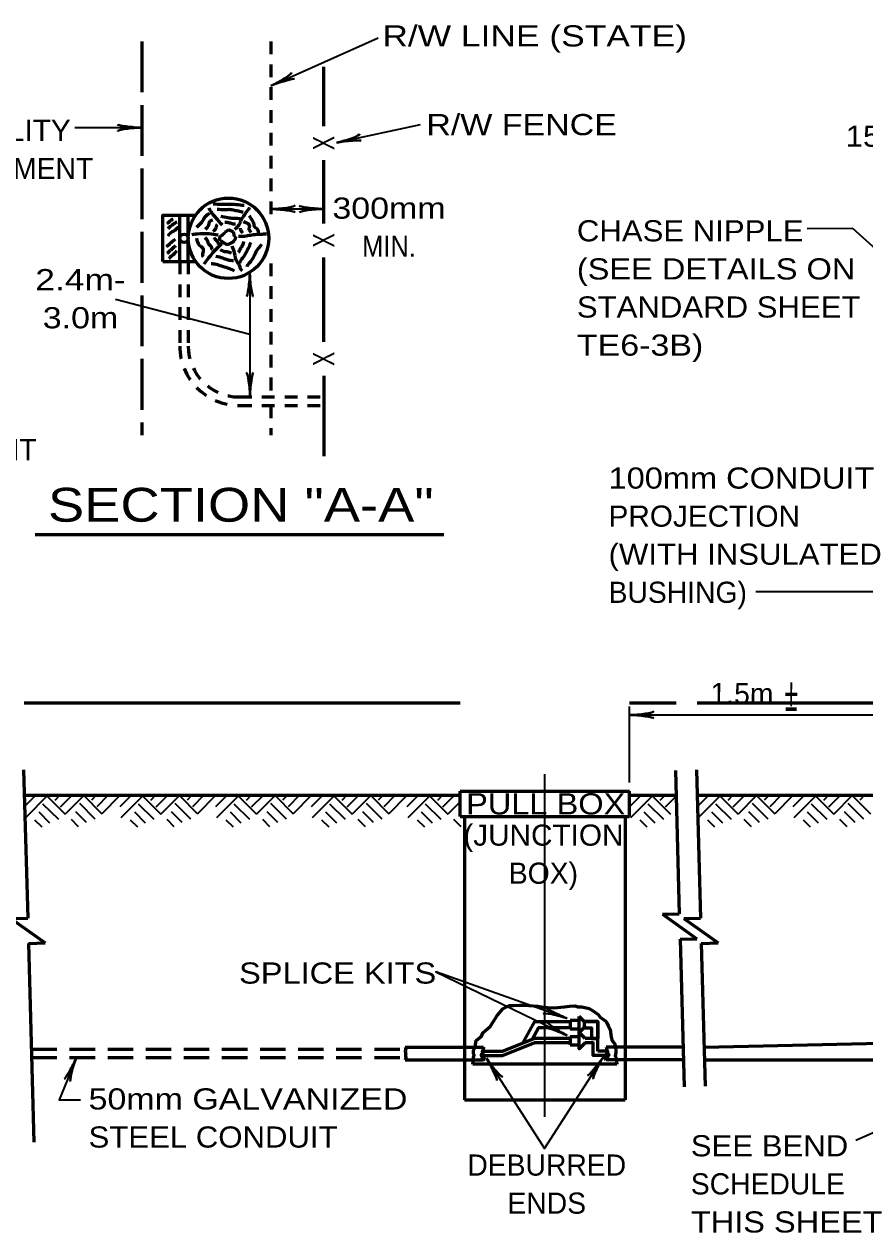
# Model space of a CAD drawing. Extents: x -111 to 744, y -77 to 467.
# Drawn here: x 90.6 to 209.8, y 149.5 to 320.9 of the extents above; entities that cross this region are included whole.
import ezdxf
from ezdxf.enums import TextEntityAlignment as Align

# ---------------------------------------------------------------- set-up
doc = ezdxf.new("R2010")
doc.units = 0
doc.header["$LTSCALE"] = 1.2
for name, pattern in [('LONG_DASHED', [7.5, 6, -1.5]), ('MEDIUM_DASHED', [4.5, 3, -1.5]), ('SHORT_DASHED', [2.7, 1.5, -1.2])]:
    doc.linetypes.add(name, pattern=pattern)
doc.layers.add('1', color=7, linetype='Continuous', lineweight=53)

msp = doc.modelspace()

# ---------------------------------------------------------------- linework, layer by layer
at = {"layer": '1', "lineweight": 35}
for p, q in [((125.55, 312.119), (140.793, 318.948)), ((107.25, 306.191), (97.784, 306.191)), ((134.901, 304.08), (146.774, 306.631)), ((125.55, 294.666), (133.05, 294.666)), ((208.049, 291.917), (201.596, 291.865)), ((232.956, 269.288), (208.049, 291.917)), ((122.588, 285.687), (122.588, 268.01)), ((122.588, 276.849), (103.55, 281.816)), ((218.647, 240.391), (194.294, 240.391)), ((176.408, 213.331), (176.408, 224.131)), ((176.408, 222.931), (214.639, 222.931)), ((164.408, 165.93), (164.408, 214.531)), ((92.192, 211.483), (90.608, 209.899)), ((93.896, 211.483), (90.752, 208.339)), ((93.776, 211.483), (96.416, 208.843)), ((95.6, 211.483), (94.928, 210.787)), ((97.328, 211.483), (95.672, 209.827)), ((99.032, 211.483), (96.416, 208.843)), ((99.032, 211.483), (101.6, 208.915)), ((100.736, 211.483), (100.112, 210.859)), ((102.464, 211.483), (100.88, 209.899)), ((104.168, 211.483), (101.6, 208.915)), ((105.752, 211.483), (104.168, 209.899)), ((107.456, 211.483), (104.312, 208.339)), ((107.336, 211.483), (109.976, 208.843)), ((109.16, 211.483), (108.488, 210.787)), ((110.888, 211.483), (109.232, 209.827)), ((112.592, 211.483), (109.976, 208.843)), ((112.592, 211.483), (115.16, 208.915)), ((114.296, 211.483), (113.672, 210.859)), ((116.024, 211.483), (114.44, 209.899)), ((117.728, 211.483), (115.16, 208.915)), ((119.312, 211.483), (117.728, 209.899)), ((121.016, 211.483), (117.872, 208.339)), ((120.896, 211.483), (123.536, 208.843)), ((122.72, 211.483), (122.048, 210.787)), ((124.448, 211.483), (122.792, 209.827)), ((126.152, 211.483), (123.536, 208.843)), ((126.152, 211.483), (128.72, 208.915)), ((127.856, 211.483), (127.232, 210.859)), ((129.584, 211.483), (128, 209.899)), ((131.288, 211.483), (128.72, 208.915)), ((132.872, 211.483), (131.288, 209.899)), ((134.576, 211.483), (131.432, 208.339)), ((134.456, 211.483), (137.096, 208.843)), ((136.28, 211.483), (135.608, 210.787)), ((138.008, 211.483), (136.352, 209.827)), ((139.712, 211.483), (137.096, 208.843)), ((139.712, 211.483), (142.28, 208.915)), ((141.416, 211.483), (140.792, 210.859)), ((143.144, 211.483), (141.56, 209.899)), ((144.848, 211.483), (142.28, 208.915)), ((146.432, 211.483), (144.848, 209.899)), ((148.136, 211.483), (144.992, 208.339)), ((148.016, 211.483), (150.656, 208.843)), ((149.84, 211.483), (149.168, 210.787)), ((151.568, 211.483), (149.912, 209.827)), ((177.992, 211.483), (176.408, 209.899)), ((179.696, 211.483), (176.552, 208.339)), ((179.576, 211.483), (182.216, 208.843)), ((181.4, 211.483), (180.728, 210.787)), ((183.128, 211.483), (181.472, 209.827)), ((187.592, 211.483), (186.008, 209.899)), ((189.296, 211.483), (186.152, 208.339)), ((189.176, 211.483), (191.816, 208.843)), ((191, 211.483), (190.328, 210.787)), ((192.728, 211.483), (191.072, 209.827)), ((194.432, 211.483), (191.816, 208.843)), ((194.432, 211.483), (197, 208.915)), ((196.136, 211.483), (195.512, 210.859)), ((197.864, 211.483), (196.28, 209.899)), ((199.568, 211.483), (197, 208.915)), ((201.152, 211.483), (199.568, 209.899)), ((202.856, 211.483), (199.712, 208.339)), ((202.736, 211.483), (205.376, 208.843)), ((204.56, 211.483), (203.888, 210.787)), ((206.288, 211.483), (204.632, 209.827)), ((207.992, 211.483), (205.376, 208.843)), ((207.992, 211.483), (210.56, 208.915)), ((209.696, 211.483), (209.072, 210.859)), ((92.648, 209.179), (94.184, 207.643)), ((93.2, 210.331), (95.432, 208.123)), ((97.856, 209.251), (99.392, 207.715)), ((98.408, 210.403), (100.616, 208.195)), ((106.208, 209.179), (107.744, 207.643)), ((106.76, 210.331), (108.992, 208.123)), ((111.416, 209.251), (112.952, 207.715)), ((111.968, 210.403), (114.176, 208.195)), ((119.768, 209.179), (121.304, 207.643)), ((120.32, 210.331), (122.552, 208.123)), ((124.976, 209.251), (126.512, 207.715)), ((125.528, 210.403), (127.736, 208.195)), ((133.328, 209.179), (134.864, 207.643)), ((133.88, 210.331), (136.112, 208.123)), ((138.536, 209.251), (140.072, 207.715)), ((139.088, 210.403), (141.296, 208.195)), ((146.888, 209.179), (148.424, 207.643)), ((147.44, 210.331), (149.672, 208.123)), ((152.408, 210.611), (150.656, 208.843)), ((178.448, 209.179), (179.984, 207.643)), ((179, 210.331), (181.232, 208.123)), ((188.048, 209.179), (189.584, 207.643)), ((188.6, 210.331), (190.832, 208.123)), ((193.256, 209.251), (194.792, 207.715)), ((193.808, 210.403), (196.016, 208.195)), ((201.608, 209.179), (203.144, 207.643)), ((202.16, 210.331), (204.392, 208.123)), ((206.816, 209.251), (208.352, 207.715)), ((207.368, 210.403), (209.576, 208.195)), ((92.048, 208.075), (93.08, 207.067)), ((97.232, 208.147), (98.264, 207.115)), ((105.608, 208.075), (106.64, 207.067)), ((110.792, 208.147), (111.824, 207.115)), ((119.168, 208.075), (120.2, 207.067)), ((124.352, 208.147), (125.384, 207.115)), ((132.728, 208.075), (133.76, 207.067)), ((137.912, 208.147), (138.944, 207.115)), ((146.288, 208.075), (147.32, 207.067)), ((151.472, 208.147), (152.504, 207.115)), ((177.848, 208.075), (178.88, 207.067)), ((187.448, 208.075), (188.48, 207.067)), ((192.632, 208.147), (193.664, 207.115)), ((201.008, 208.075), (202.04, 207.067)), ((206.192, 208.147), (207.224, 207.115))]:
    msp.add_line(p, q, dxfattribs=at)
at = {"layer": '1', "linetype": 'LONG_DASHED'}
msp.add_line((107.25, 318.41), (107.25, 262.61), dxfattribs=at)
at = {"layer": '1', "linetype": 'SHORT_DASHED'}
for p, q in [((125.55, 318.41), (125.55, 292.897)), ((112.65, 287.21), (112.65, 275.21)), ((113.85, 287.21), (113.85, 275.21)), ((125.55, 286.952), (125.55, 268.01)), ((121.05, 268.01), (133.05, 268.01)), ((121.05, 266.81), (133.05, 266.81)), ((125.55, 266.81), (125.55, 262.61))]:
    msp.add_line(p, q, dxfattribs=at)
at = {"layer": '1'}
for p, q in [((133.05, 306.41), (133.05, 314.81)), ((133.05, 292.61), (133.05, 301.61)), ((112.65, 287.21), (112.65, 293.81)), ((113.85, 287.21), (113.85, 293.81)), ((110.25, 287.21), (114.902, 287.21)), ((133.05, 275.81), (133.05, 287.81)), ((133.05, 271.01), (133.05, 259.61)), ((92.14, 248.5), (150.088, 248.5)), ((90.608, 224.648), (152.408, 224.648)), ((176.408, 224.648), (183.008, 224.648)), ((186.008, 224.648), (214.639, 224.648)), ((90.509, 215.129), (91.087, 194.13)), ((182.912, 215.047), (183.47, 194.73)), ((185.91, 215.129), (186.487, 194.13)), ((90.608, 211.531), (152.408, 211.531)), ((152.408, 208.531), (152.408, 212.131)), ((152.408, 212.131), (176.408, 212.131)), ((176.408, 208.531), (176.408, 212.131)), ((176.408, 211.531), (183.008, 211.531)), ((186.008, 211.531), (214.639, 211.531)), ((152.408, 208.531), (176.408, 208.531)), ((153.008, 208.531), (153.008, 168.331)), ((175.808, 208.531), (175.808, 168.331)), ((88.688, 194.064), (91.087, 194.13)), ((88.688, 194.064), (93.585, 190.597)), ((181.071, 194.664), (183.47, 194.73)), ((181.071, 194.664), (185.968, 191.197)), ((184.088, 194.064), (186.487, 194.13)), ((184.088, 194.064), (188.985, 190.597)), ((91.186, 190.531), (93.585, 190.597)), ((91.186, 190.531), (91.961, 162.335)), ((183.569, 191.131), (185.968, 191.197)), ((183.569, 191.131), (184.145, 170.207)), ((186.586, 190.531), (188.985, 190.597)), ((186.586, 190.531), (187.142, 170.29)), ((170.115, 179.321), (169.26, 180.176)), ((169.26, 177.879), (169.26, 180.176)), ((168.007, 179.627), (169.26, 179.627)), ((168.007, 178.428), (169.26, 178.428)), ((170.212, 178.831), (169.26, 177.879)), ((158.408, 175.231), (162.908, 177.031)), ((168.007, 177.031), (162.908, 177.031)), ((168.007, 177.331), (168.007, 176.131)), ((168.007, 177.331), (169.26, 177.331)), ((170.108, 177.031), (169.26, 177.879)), ((171.908, 177.031), (170.108, 177.031)), ((171.908, 175.231), (171.908, 177.031)), ((144.608, 175.831), (155.708, 175.831)), ((155.503, 175.231), (158.408, 175.231)), ((158.408, 174.631), (162.908, 176.43)), ((168.007, 176.43), (162.908, 176.43)), ((168.007, 176.131), (169.26, 176.131)), ((173.314, 175.231), (171.908, 175.231)), ((183.99, 175.831), (173.108, 175.831)), ((186.99, 175.831), (214.639, 176.43)), ((144.608, 174.031), (155.708, 174.031)), ((174.608, 173.43), (154.208, 173.43)), ((155.829, 174.631), (158.408, 174.631)), ((184.039, 174.031), (173.108, 174.031)), ((187.039, 174.031), (214.639, 174.031)), ((153.008, 168.331), (175.808, 168.331))]:
    msp.add_line(p, q, dxfattribs=at)
at = {"layer": '1', "linetype": 'MEDIUM_DASHED'}
for p, q in [((91.631, 175.531), (144.709, 175.531)), ((91.631, 174.331), (144.752, 174.331))]:
    msp.add_line(p, q, dxfattribs=at)
at = {"layer": '1'}
for points in [[(110.25, 287.21), (110.25, 293.81), (114.902, 293.81)], [(154.208, 173.43), (154.288, 174.356), (154.407, 174.674), (154.288, 174.873), (154.288, 175.39), (154.526, 175.788), (154.606, 176.464), (154.685, 176.782), (155.441, 177.379), (155.68, 177.896), (156.674, 178.771), (157.191, 179.567), (157.668, 180.323), (158.026, 180.721), (158.463, 181.238), (158.94, 181.556), (159.457, 181.715), (159.974, 181.715), (160.929, 181.755), (161.605, 181.755), (162.121, 181.715), (163.394, 181.635), (163.951, 181.516), (164.388, 181.476), (164.746, 181.436), (165.7, 181.397), (167.211, 181.556), (167.967, 181.635), (168.643, 181.675), (169.08, 181.556), (169.637, 181.516), (170.711, 181.317), (171.148, 181.039), (171.944, 180.442), (172.262, 180.084), (172.938, 179.567), (173.176, 179.288), (173.375, 178.851), (173.653, 178.334), (173.812, 177.22), (173.932, 176.703), (174.29, 176.345), (174.369, 175.987), (174.409, 175.788), (174.449, 175.311), (174.449, 175.072), (174.409, 174.754), (174.369, 174.555), (174.568, 174.197), (174.568, 173.879), (174.608, 173.43)], [(168.007, 179.627), (168.007, 178.578), (168.007, 178.428)], [(169.958, 179.478), (171.908, 179.478), (171.908, 177.031)], [(170.108, 176.43), (169.26, 175.582), (169.26, 177.879)], [(144.608, 175.831), (144.663, 175.741), (144.642, 175.648), (144.677, 175.542), (144.698, 175.506), (144.663, 175.428), (144.642, 175.379), (144.613, 175.251), (144.67, 175.116), (144.663, 175.002), (144.642, 174.932), (144.663, 174.804), (144.698, 174.697), (144.656, 174.633), (144.635, 174.527), (144.698, 174.421), (144.713, 174.335), (144.684, 174.272), (144.663, 174.194), (144.608, 174.031)], [(155.708, 175.831), (155.695, 175.648), (155.638, 175.577), (155.667, 175.464), (155.567, 175.322), (155.553, 175.308), (155.539, 175.208), (155.539, 175.152), (155.553, 175.066), (155.553, 174.967), (155.454, 174.839), (155.369, 174.782), (155.354, 174.754), (155.369, 174.641), (155.482, 174.527), (155.511, 174.513), (155.511, 174.456), (155.511, 174.186), (155.482, 174.144), (155.482, 174.101), (155.496, 174.03)], [(155.708, 174.031), (155.809, 174.13), (155.794, 174.215), (155.738, 174.3), (155.752, 174.399), (155.794, 174.527), (155.752, 174.655), (155.723, 174.74), (155.667, 174.811), (155.567, 174.91), (155.525, 174.953)], [(172.988, 174.631), (171.268, 174.631), (171.268, 176.43), (170.108, 176.43)], [(173.108, 174.031), (173.008, 174.13), (173.023, 174.215), (173.079, 174.3), (173.065, 174.399), (173.023, 174.527), (173.065, 174.655), (173.093, 174.74), (173.15, 174.811), (173.25, 174.91), (173.292, 174.953)], [(173.108, 175.831), (173.122, 175.648), (173.179, 175.577), (173.15, 175.464), (173.25, 175.322), (173.264, 175.308), (173.278, 175.208), (173.278, 175.152), (173.264, 175.066), (173.264, 174.967), (173.363, 174.839), (173.448, 174.782), (173.462, 174.754), (173.448, 174.641), (173.335, 174.527), (173.306, 174.513), (173.306, 174.456), (173.306, 174.186), (173.335, 174.144), (173.335, 174.101), (173.321, 174.03)]]:
    msp.add_lwpolyline(points, dxfattribs=at)
at = {"layer": '1', "lineweight": 35}
for points in [[(167.577, 179.885), (148.963, 186.504), (167.577, 177.473)], [(228.628, 176.842), (231.996, 172.918), (208.514, 162.599)], [(98.009, 174.331), (95.526, 168.335), (98.575, 168.335)], [(156.136, 174.256), (164.361, 161.451), (172.709, 174.442)]]:
    msp.add_lwpolyline(points, dxfattribs=at)
at = {"layer": '1'}
for points in [[(162.585, 176.901), (161.268, 176.374), (162.975, 179.478), (168.007, 179.478), (168.007, 178.578), (163.507, 178.578), (162.585, 176.901), (162.908, 177.031)], [(169.958, 179.478), (169.958, 178.578), (171.008, 178.578), (171.008, 177.031), (171.908, 177.031), (171.908, 179.478)]]:
    msp.add_lwpolyline(points, close=True, dxfattribs=at)
for centre, radius in [((119.55, 290.51), 5.7), ((113.25, 290.51), 0.6)]:
    msp.add_circle(centre, radius, dxfattribs=at)
at = {"layer": '1', "linetype": 'SHORT_DASHED'}
for radius in [8.4, 7.2]:
    msp.add_arc((121.05, 275.21), radius, 180, 270, dxfattribs=at)
at = {"layer": '1', "lineweight": 40}
for centre, major_axis, ratio, start_param, end_param in [((126.609, 312.957), (-1.879, -1.047), 0.122415, 0.8963533, 3.1415927), ((126.609, 312.957), (-1.879, -1.047), 0.122415, 0.8963533, 3.1415927), ((126.881, 312.437), (-2.01, -0.669), 0.07063, 3.1407148, 5.41811), ((126.881, 312.437), (-2.01, -0.669), 0.07063, 3.1407148, 5.41811), ((105.941, 305.86), (2.143, 0.187), 0.122415, 0.8963533, 3.1415927), ((105.941, 305.86), (2.143, 0.187), 0.122415, 0.8963533, 3.1415927), ((105.905, 306.445), (2.108, -0.211), 0.07063, 3.1407148, 5.41811), ((105.905, 306.445), (2.108, -0.211), 0.07063, 3.1407148, 5.41811), ((136.111, 304.679), (-2.056, -0.633), 0.122415, 0.8963533, 3.1415927), ((136.111, 304.679), (-2.056, -0.633), 0.122415, 0.8963533, 3.1415927), ((136.269, 304.114), (-2.105, -0.237), 0.07063, 3.1407148, 5.41811), ((136.269, 304.114), (-2.105, -0.237), 0.07063, 3.1407148, 5.41811), ((126.859, 294.998), (-2.143, -0.187), 0.122415, 0.8963533, 3.1415927), ((126.859, 294.998), (-2.143, -0.187), 0.122415, 0.8963533, 3.1415927), ((131.705, 294.92), (2.108, -0.211), 0.07063, 3.1407148, 5.41811), ((131.705, 294.92), (2.108, -0.211), 0.07063, 3.1407148, 5.41811), ((126.895, 294.412), (-2.108, 0.211), 0.07063, 3.1407148, 5.41811), ((126.895, 294.412), (-2.108, 0.211), 0.07063, 3.1407148, 5.41811), ((131.741, 294.334), (2.143, 0.187), 0.122415, 0.8963533, 3.1415927), ((131.741, 294.334), (2.143, 0.187), 0.122415, 0.8963533, 3.1415927), ((122.334, 284.342), (0.211, 2.108), 0.07063, 3.1407148, 5.41811), ((122.334, 284.342), (0.211, 2.108), 0.07063, 3.1407148, 5.41811), ((122.919, 284.378), (-0.187, 2.143), 0.122415, 0.8963533, 3.1415927), ((122.919, 284.378), (-0.187, 2.143), 0.122415, 0.8963533, 3.1415927), ((122.256, 269.32), (0.187, -2.143), 0.122415, 0.8963533, 3.1415927), ((122.842, 269.355), (-0.211, -2.108), 0.07063, 3.1407148, 5.41811), ((177.753, 222.677), (-2.108, 0.211), 0.07063, 3.1407148, 5.41811), ((177.753, 222.677), (-2.108, 0.211), 0.07063, 3.1407148, 5.41811), ((177.718, 223.262), (-2.143, -0.187), 0.122415, 0.8963533, 3.1415927), ((177.718, 223.262), (-2.143, -0.187), 0.122415, 0.8963533, 3.1415927), ((166.232, 180.012), (2.082, -0.541), 0.122415, 0.8963533, 3.1415927), ((166.395, 180.575), (-1.915, 0.905), 0.07063, 6.2823074, 8.5597026), ((166.254, 177.746), (2.01, -0.767), 0.122415, 0.8963533, 3.1415927), ((166.478, 178.288), (1.804, -1.11), 0.07063, 3.1407148, 5.41811), ((97.26, 173.185), (-1.001, -1.867), 0.07063, 6.2823074, 8.5597026), ((97.815, 172.994), (0.647, 2.051), 0.122415, 0.8963533, 3.1415927), ((156.649, 172.987), (0.962, -1.887), 0.07063, 6.2823074, 8.5597026), ((156.649, 172.987), (0.962, -1.887), 0.07063, 6.2823074, 8.5597026), ((157.123, 173.333), (-1.316, 1.702), 0.122415, 0.8963533, 3.1415927), ((157.123, 173.333), (-1.316, 1.702), 0.122415, 0.8963533, 3.1415927), ((171.769, 173.448), (-1.317, -1.659), 0.07063, 6.2823074, 8.5597026), ((172.28, 173.161), (1.001, 1.904), 0.122415, 0.8963533, 3.1415927)]:
    msp.add_ellipse(centre, major_axis=major_axis, ratio=ratio, start_param=start_param, end_param=end_param, dxfattribs=at)
at = {"layer": '1'}
for points in [[(117.372, 295.383), (118.692, 295.365), (119.512, 295.365), (120.653, 295.312), (121.776, 295.187)], [(120.457, 291.816), (121.045, 292.422), (121.366, 293.082), (121.812, 293.813), (122.472, 294.723), (122.596, 294.866)], [(111.72, 293.278), (111.256, 292.957), (110.828, 292.547)], [(115.054, 292.083), (115.964, 293.082), (116.302, 293.617), (116.926, 294.081)], [(116.285, 291.816), (116.766, 292.422), (116.909, 292.922), (117.337, 293.136)], [(118.692, 292.351), (117.782, 293.421), (117.283, 294.01), (116.819, 294.759)], [(117.943, 294.652), (119.084, 294.58), (119.833, 294.616), (120.582, 294.473), (121.295, 294.331), (121.634, 294.224)], [(118.46, 293.653), (119.458, 293.457), (120.225, 293.368), (120.796, 293.368), (121.241, 293.296)], [(122.472, 293.742), (122.864, 293.118), (123.149, 292.476), (123.203, 292.208), (123.666, 291.762), (123.773, 291.263)], [(112.219, 292.815), (111.72, 292.494), (111.417, 292.28), (110.971, 291.869)], [(112.398, 292.101), (111.952, 291.637), (111.595, 291.441), (111.114, 291.049), (110.971, 290.835)], [(117.39, 291.512), (117.782, 291.905), (117.907, 292.369), (117.996, 292.476)], [(119.013, 292.797), (119.69, 292.725), (120.172, 292.583), (120.492, 292.547), (120.528, 292.547)], [(121.188, 291.958), (121.348, 291.53), (121.544, 291.298)], [(121.669, 292.904), (122.525, 292.19), (122.454, 291.78), (122.614, 291.53), (122.703, 291.334)], [(111.987, 290.335), (111.47, 289.943), (111.149, 289.64), (110.739, 289.301)], [(118.068, 290.942), (116.766, 291.138), (115.072, 291.102), (114.359, 291.013)], [(115.019, 290.531), (115.411, 289.55), (115.91, 289.105), (115.91, 288.463), (115.892, 288.052), (115.981, 287.945)], [(118.549, 289.711), (117.604, 288.766), (116.623, 287.589), (116.035, 286.822)], [(116.178, 290.621), (116.588, 290.121), (116.73, 289.711), (117.105, 289.337), (117.158, 289.087), (117.176, 288.998), (117.212, 288.962)], [(117.533, 290.603), (117.764, 290.282), (118.014, 290.032), (118.085, 289.693), (118.085, 289.64)], [(121.687, 290.05), (121.366, 289.23), (121.206, 289.015), (121.081, 288.73), (120.92, 288.498)], [(120.956, 290.817), (122.079, 290.853), (122.846, 291.013), (123.862, 291.084), (124.486, 291.12), (124.932, 291.156)], [(122.739, 289.907), (122.365, 289.123), (122.008, 288.445), (121.562, 287.696), (121.134, 287), (121.134, 286.982)], [(124.237, 289.64), (123.452, 288.587), (123.185, 288.035), (122.686, 287.196), (122.186, 286.608), (122.133, 286.5)], [(112.041, 289.426), (111.595, 289.051), (111.238, 288.712), (110.971, 288.463), (110.846, 288.373)], [(112.184, 288.748), (111.666, 288.124), (111.435, 287.981), (111.256, 287.767), (111.114, 287.642)], [(117.782, 287.963), (118.745, 287.731), (119.369, 287.482), (119.886, 287.392), (120.261, 287.357)], [(118.388, 288.926), (118.995, 288.659), (119.476, 288.605), (119.797, 288.48), (119.975, 288.391)], [(120.029, 289.461), (120.368, 288.463), (120.813, 287.071), (121.045, 286.768), (121.241, 286.18), (121.491, 285.93)], [(117.087, 286.946), (117.8, 286.839), (118.567, 286.59), (119.405, 286.34), (120.065, 286.072), (120.368, 285.912)]]:
    msp.add_spline(points, degree=3, dxfattribs=at)
at = {"layer": '1', "linetype": 'LONG_DASHED'}
msp.add_spline([(119.565, 291.744), (119.779, 291.637), (120.136, 291.477), (120.279, 291.227), (120.35, 290.835), (120.564, 290.603), (120.475, 290.425), (120.421, 290.282), (120.225, 290.014), (119.815, 289.765), (119.405, 289.622), (119.084, 289.729), (118.567, 290.086), (118.317, 290.425), (118.353, 290.71), (118.656, 290.977), (118.923, 291.174), (119.244, 291.53), (119.512, 291.691)], degree=3, dxfattribs=at)

# ---------------------------------------------------------------- texts
at = {"layer": '1'}
for s, height, width, p in [('R/W LINE (STATE)', 3, 1.25, (162.956, 317.712)), ('UTILITY', 3, 1.05, (89.343, 304.312)), ('R/W FENCE', 3, 1.2, (161.11, 305.131)), ('150mm', 3, 1.1, (214.413, 303.491)), ('300mm', 3, 1.2, (142.31, 293.288)), ('MIN.', 3, 0.9, (142.31, 287.887)), ('2.4m-', 3, 1.25, (98.572, 283.144)), ('3.0m', 3, 1.2, (98.572, 277.744)), ('SECTION "A-A"', 4.8, 1.2, (121.301, 250.325)), ('(JUNCTION', 3, 1.05, (164.201, 204.388))]:
    msp.add_text(s, height=height, dxfattribs=dict(at, width=width)).set_placement(p, align=Align.CENTER)
for s, height, rotation, width, p in [('X', 3, 90, 0.75, (134.55, 304.01)), ('X', 3, 90, 0.75, (134.55, 290.21)), ('X', 3, 90, 0.75, (134.55, 273.41)), ('+', 4.8, 359.477, 0.55, (199.314, 223.525))]:
    msp.add_text(s, height=height, rotation=rotation, dxfattribs=dict(at, width=width)).set_placement(p, align=Align.CENTER)
for s, p in [('EASEMENT', (89.343, 298.912)), ('BOX)', (164.201, 198.988)), ('DEBURRED', (164.674, 157.601)), ('ENDS', (164.674, 152.201))]:
    msp.add_text(s, height=3, dxfattribs=at).set_placement(p, align=Align.CENTER)
for s, width, p in [('CHASE NIPPLE', 1.1, (168.944, 290.069)), ('(SEE DETAILS ON', 1.15, (168.944, 284.669)), ('STANDARD SHEET', 1.1, (168.944, 279.269)), ('TE6-3B)', 1.2, (168.944, 273.869)), ('100mm CONDUIT', 1.15, (173.438, 255.015)), ('PROJECTION', 1.05, (173.438, 249.615)), ('(WITH INSULATED', 1.1, (173.438, 244.215)), ('PULL BOX', 1.15, (153.246, 208.818)), ('SPLICE KITS', 1.15, (121.059, 184.83)), ('50mm GALVANIZED', 1.2, (99.716, 166.977)), ('STEEL CONDUIT', 1.1, (99.716, 161.577)), ('SEE BEND', 1.1, (185.099, 160.334)), ('THIS SHEET', 1.15, (185.099, 149.534))]:
    msp.add_text(s, height=3, dxfattribs=dict(at, width=width)).set_placement(p)
for s, p in [('CONDUIT', (74.102, 259.032)), ('BUSHING)', (173.438, 238.815)), ('SCHEDULE', (185.099, 154.934))]:
    msp.add_text(s, height=3, dxfattribs=at).set_placement(p)
for s, height, p in [('1.5m', 3, (192.34, 224.446)), ('-', 4.8, (199.304, 221.893))]:
    msp.add_text(s, height=height, rotation=359.477, dxfattribs=at).set_placement(p, align=Align.CENTER)

doc.saveas('drawing.dxf')
